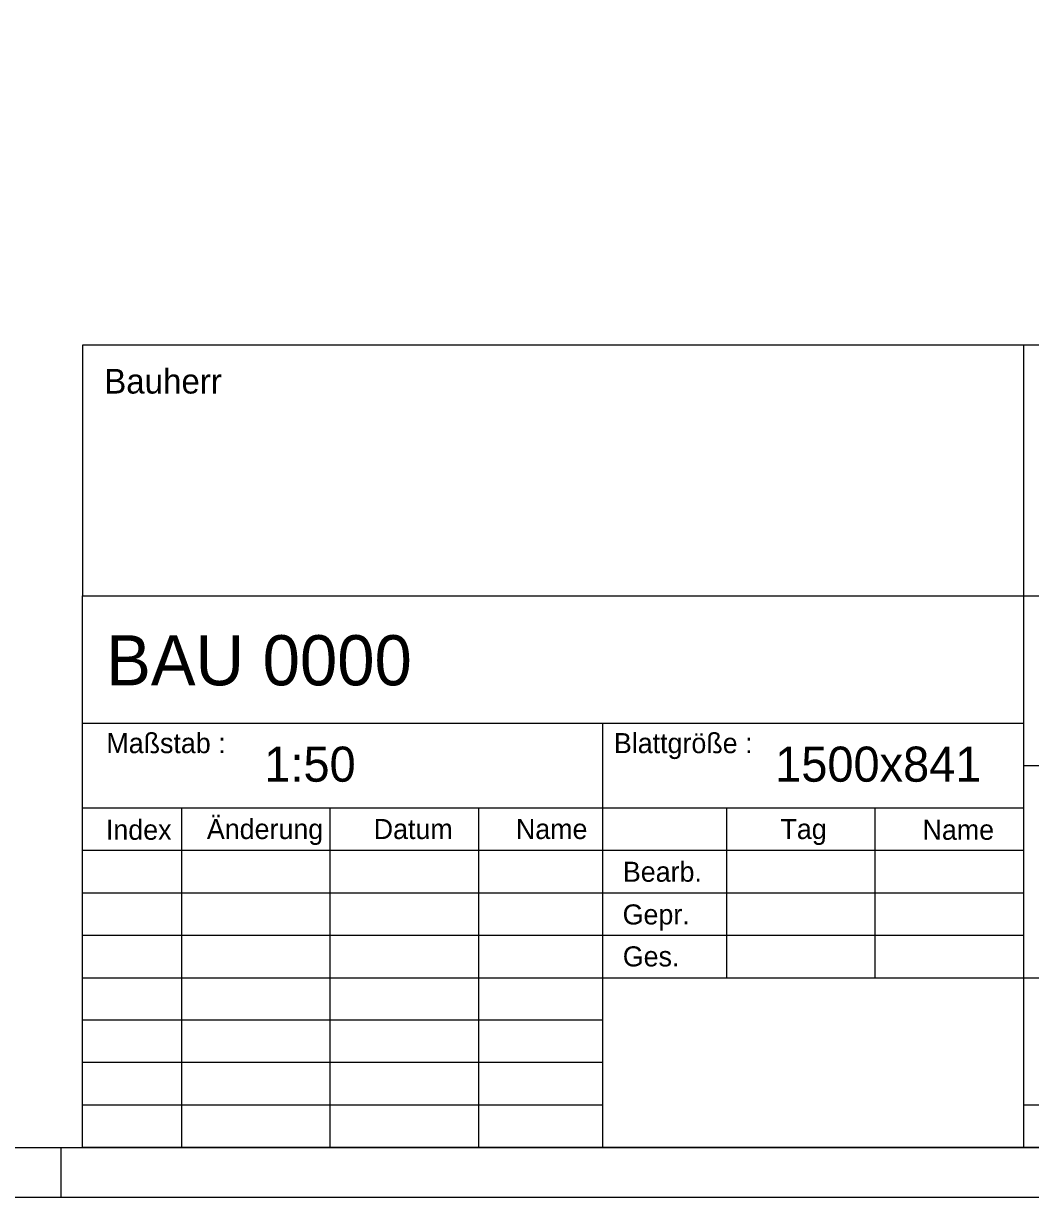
# Model space of a CAD drawing. Extents: x 0 to 75, y 0 to 42.1.
# Drawn here: x 65.56 to 70.58, y 0 to 5.85 of the extents above; entities that cross this region are included whole.
import ezdxf

# ---------------------------------------------------------------- set-up
doc = ezdxf.new("R2010")
doc.units = 0
doc.layers.add('90_Plankopf', color=7, linetype='Continuous')

msp = doc.modelspace()

# ---------------------------------------------------------------- linework, layer by layer
at = {"layer": '90_Plankopf'}
for p, q in [((74.75, 4.2495), (65.856, 4.2495)), ((65.856, 4.2495), (65.856, 2.9995)), ((70.55, 2.9995), (70.55, 4.2495)), ((65.856, 2.9995), (74.75, 2.9995)), ((65.856, 0.25), (65.856, 2.9995)), ((65.856, 2.9995), (74.75, 2.9995)), ((70.55, 0.25), (70.55, 2.9995)), ((65.856, 2.365), (70.55, 2.365)), ((68.4501, 0.25), (68.4501, 2.365)), ((70.55, 2.1535), (74.75, 2.1535)), ((65.856, 1.9435), (70.55, 1.9435)), ((66.3501, 1.942), (66.3501, 0.25)), ((67.0913, 0.25), (67.0913, 1.942)), ((67.8325, 0.25), (67.8325, 1.942)), ((69.0677, 1.942), (69.0677, 1.096)), ((69.8089, 1.096), (69.8089, 1.942)), ((65.856, 1.7315), (70.55, 1.7315)), ((65.856, 1.519), (70.55, 1.519)), ((65.856, 1.3075), (70.55, 1.3075)), ((65.856, 1.096), (70.55, 1.096)), ((65.856, 1.096), (70.55, 1.096)), ((68.4501, 1.096), (70.55, 1.096)), ((70.55, 1.096), (74.75, 1.096)), ((68.4501, 0.8845), (65.856, 0.8845)), ((68.4501, 0.673), (65.856, 0.673)), ((65.856, 0.4615), (68.4501, 0.4615)), ((70.55, 0.4615), (74.75, 0.4615)), ((65.75, 0), (65.75, 0.25)), ((74.75, 0.25), (65.856, 0.25)), ((65.856, 0.25), (68.4501, 0.25)), ((66.44, 0.25), (74.75, 0.25)), ((66.44, 0.25), (74.75, 0.25))]:
    msp.add_line(p, q, dxfattribs=at)
msp.add_lwpolyline([(0, 42.05), (75, 42.05), (75, 0), (0, 0)], close=True, dxfattribs=at)
msp.add_lwpolyline([(59.6038, 0.25), (74.75, 0.25), (74.75, 41.8), (59.6038, 41.8)], dxfattribs=at)

# ---------------------------------------------------------------- texts
for s, height, p in [('Bauherr', 0.12318, (65.9652, 4.0088)), ('BAU 0000      ', 0.25, (65.9745, 2.5538)), ('Maßstab :', 0.1, (65.9758, 2.2158)), ('Blattgröße :', 0.099995, (68.5058, 2.2158)), ('1:50     ', 0.175, (66.7631, 2.0734)), ('1500x841 ', 0.175, (69.31, 2.0734)), ('Index', 0.1, (65.9734, 1.7837)), ('Änderung', 0.1, (66.4767, 1.7875)), ('Datum', 0.1, (67.3084, 1.7875)), ('Name', 0.1, (68.0174, 1.7875)), ('Tag', 0.1, (69.3362, 1.7875)), ('Name', 0.1, (70.0446, 1.7837)), ('Bearb.', 0.1, (68.5507, 1.5745)), ('Gepr.', 0.1, (68.5495, 1.3615)), ('Ges.', 0.1, (68.5502, 1.1523))]:
    msp.add_text(s, height=height, dxfattribs=at).set_placement(p)

doc.saveas('drawing.dxf')
